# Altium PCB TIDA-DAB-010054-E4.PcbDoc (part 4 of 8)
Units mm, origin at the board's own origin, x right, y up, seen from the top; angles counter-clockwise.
Board outline 300 x 180 mm, 4 copper layers (Top Layer, Inner Layer1, Inner Layer2, Bottom Layer), stack 1.605 mm thick; 873 components, 388 nets, 2405 pads, 1542 vias.
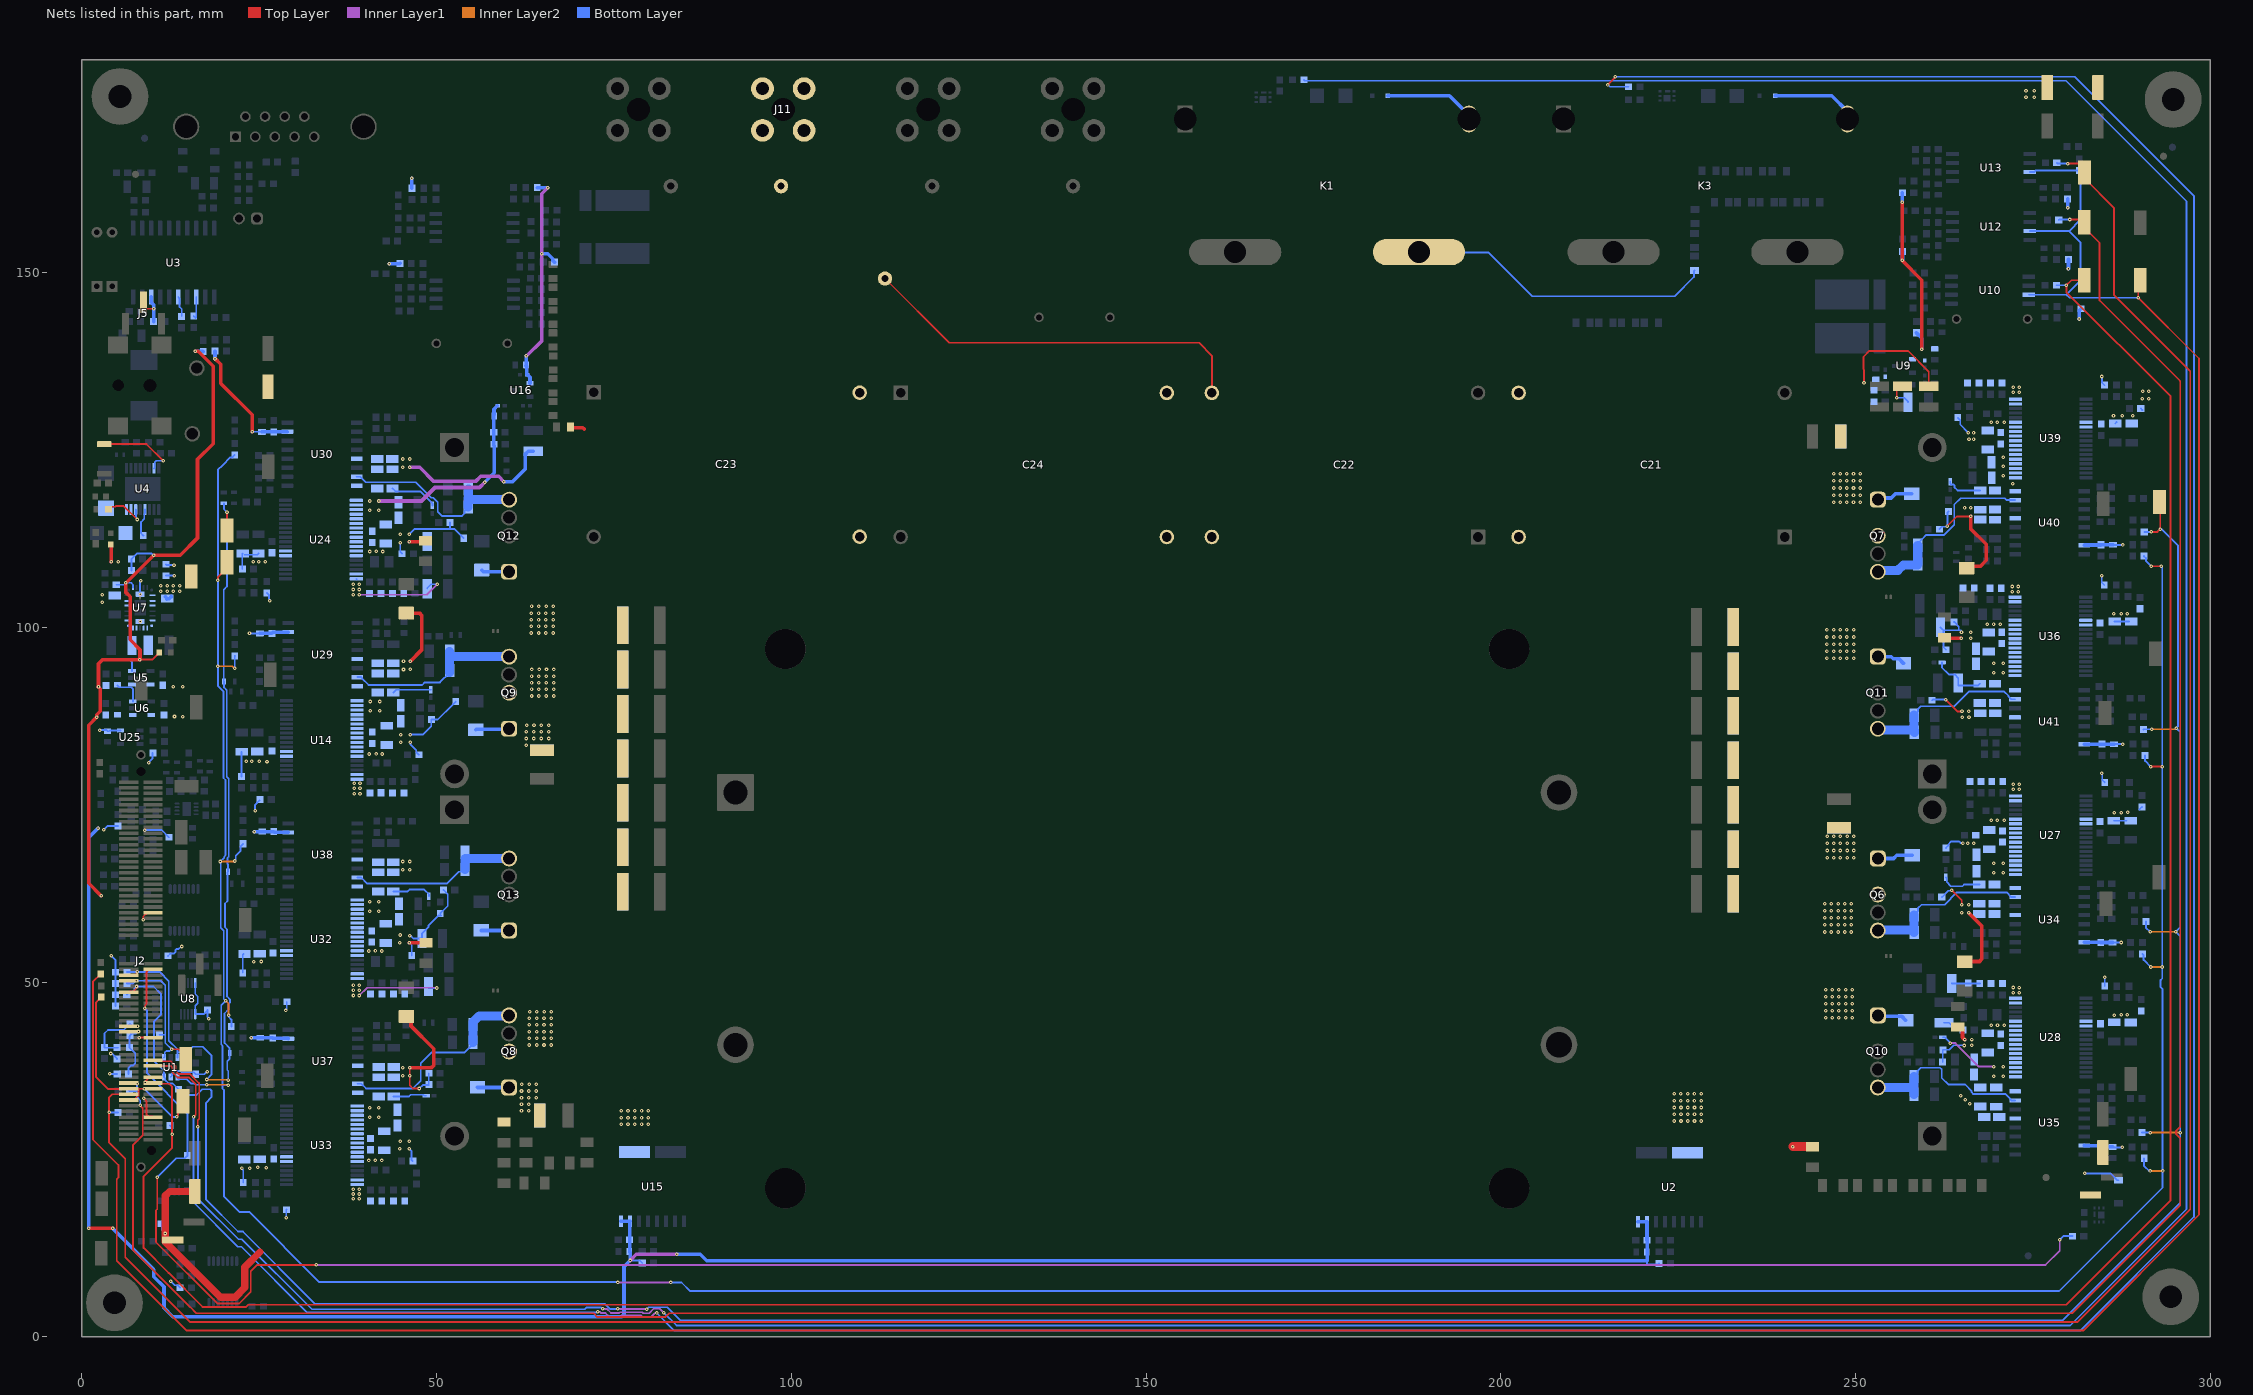
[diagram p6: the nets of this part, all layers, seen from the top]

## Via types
v1: diameter 0.5, hole 0.2, Top Layer to Bottom Layer, tented both sides, 1530 vias
v2: diameter 0.5, hole 0.2, Top Layer to Bottom Layer, 12 vias

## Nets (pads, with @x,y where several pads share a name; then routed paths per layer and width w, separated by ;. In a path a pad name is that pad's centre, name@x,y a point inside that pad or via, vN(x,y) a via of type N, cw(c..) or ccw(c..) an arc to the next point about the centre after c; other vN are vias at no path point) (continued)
3V3_A: C65.1 C110.1 C111.2 C146.1 C147.1 C148.2 L14.2 L15.1 L18.2 R15.2 R37.1 R45.1 R163.1 U2.9 U2.10 U5.5 U15.9 U15.10 U25.5 | length 322.8
  Top Layer w0.508: v1(1.016,15.308) v1(4.372,15.308)
  Inner Layer1 w0.508: v1(77.318,10.77) 78.178,11.63 v1(83.859,11.63)
  Bottom Layer w0.254: v1(2.542,85.502) 3.553,85.502 3.723,85.332 3.875,85.332 4.017,85.474 4.044,85.448 U25.5@5.475,85.448 ; v1(3.139,71.445) 3.701,72.007 R15.2@5.15,72.007 ; v1(8.878,71.409) 8.897,71.428 11.291,71.428 L15.1@12.319,70.4 ; v1(9.448,80.885) 9.448,80.951 9.987,81.49 R163.1@9.987,82.264 ; v1(77.318,10.77) 78.029,10.77 78.036,10.762 78.659,10.762 R45.1@79.007,10.414 ; 220.618,10.744 220.616,10.742 220.616,10.222 222.173,10.222 R37.1@222.288,10.338
  Bottom Layer w0.508: v1(1.016,15.308) 1.016,70.366 v1(2.325,71.675) ; v1(4.372,15.308) 10.196,9.484 10.196,8.478 11.623,7.05 11.623,4.086 12.864,2.845 76.151,2.845 76.449,3.142 76.449,9.901 v1@77.2,10.652 ; v1(43.378,151.23) 43.398,151.25 44.849,151.25 L18.2@44.884,151.285 ; L14.2@46.559,161.867 v1(46.559,163.283) ; U15.10@76.022,16.309 U15.9@77.292,16.309 ; C148.2@77.225,12.024 77.318,11.932 v1(77.318,10.77) ; C148.2@77.225,12.245 C147.1@77.225,13.702 77.275,13.752 U15.9@77.275,16.12 ; v1(83.859,11.63) 87.201,11.63 88.087,10.744 220.618,10.744 220.618,11.938 220.62,11.94 C110.1@220.62,13.62 220.603,13.638 U2.9@220.603,16.205 ; U2.10@219.315,16.205 U2.9@220.585,16.205
  other v1: 12.904,91.603 14.262,91.603
3V3_D: C1.1 C69.1 C186.2 C187.2 C191.2 C192.2 C228.2 C229.2 C233.2 C234.2 C266.2 C268.2 C274.2 C298.2 C306.2 C307.2 C310.2 C311.2 C313.1 L2.2 L8.2 L9.2 L10.2 R79.1 R82.1 R123.2 R164.2 R172.1 R185.1 R187.1 R204.1 R205.1 R230.1 R243.1 R245.1 R286.1 R291.1 R329.1 R344.1 U1.5 U6.5 U8.5 U8.6 U29.15 U30.15 U34.15 U35.15 U37.15 U38.15 U40.15 U41.15 | length 98.7
  Top Layer w0.508: v1(18.808,137.859) 19.625,137.043 19.625,134.361 24.036,129.95 v1(24.036,127.541)
  Bottom Layer w0.254: v1(3.981,37.059) R123.2@5.029,37.059 ; v1@4.136,39.98 v1(4.091,39.935) 4.138,39.888 4.321,39.888 5.004,39.205 R164.2@5.004,39.18 ; v1(4.172,53.688) 4.795,53.065 R205.1@4.795,51.39 4.769,51.364 R82.1@4.769,48.223 R79.1@4.769,46.633 ; R172.1@12.182,53.672 12.552,54.043 13.078,54.043 13.227,54.191 13.227,54.476 13.42,54.669 13.693,54.669 14.04,55.016 v1(14.106,55.016) ; v1(12.578,7.855) 13.146,7.287 13.542,7.287 R230.1@13.89,6.939 ; U1.5@12.578,36.642 12.751,36.815 12.751,37.102 13.121,37.472 13.935,37.472 14.118,37.288 15.815,37.288 C1.1@16.098,37.005 17.271,37.005 17.63,37.364 v1(17.697,37.364) ; U8.5@16.025,49.881 16.025,48.314 16.37,47.97 16.37,47.001 16.025,46.657 U8.6@16.025,45.481 17.202,45.481 C313.1@17.752,46.031 ; C313.1@17.752,46.056 C313.1@17.752,46.031 ; v1(17.929,44.809) 17.929,44.876 17.752,45.053 C313.1@17.752,46.031 ; v1(23.667,99.127) C186.2@25.134,99.127 ; v1(24.036,127.541) 25.391,127.541 C191.2@25.411,127.522 ; v1(24.46,74.143) 24.46,74.968 24.71,75.217 24.71,75.242 25.058,75.59 R185.1@25.083,75.59 ; R187.1@26.086,104.854 26.434,104.506 26.434,103.934 26.544,103.823 v1(26.544,103.757) ; v1(28.753,45.999) 28.753,46.066 28.931,46.244 R286.1@28.931,47.219 ; v1(28.854,16.815) 28.854,17.907 R291.1@28.88,17.932 ; v1(284.688,107.278) 284.688,106.302 R344.1@285.033,105.957 ; v1(284.708,79.402) 284.751,79.359 284.751,78.48 R243.1@285.099,78.132 ; v1(284.708,135.338) 284.722,135.324 284.722,134.457 R329.1@285.07,134.109 ; R245.1@285.105,49.433 v1(285.105,50.688) ; C233.2@286.199,26.783 286.283,26.699 v1(287.596,26.699) v1@287.599,26.696 ; C228.2@286.2,55.574 v1(287.425,55.574) ; C306.2@286.287,111.628 286.319,111.596 v1(287.645,111.596) ; C310.2@286.4,83.535 v1(287.625,83.535)
  Bottom Layer w0.508: v1(18.808,137.859) L2.2@18.808,138.909 ; v1(23.905,42.147) C266.2@25.19,42.147 ; v1(24.332,71.2) 25.453,71.2 C298.2@27.101,71.2 27.168,71.133 29.07,71.133 U38.15@29.116,71.087 ; C186.2@25.134,99.127 25.143,99.136 26.821,99.136 C187.2@26.83,99.145 26.96,99.274 29.07,99.274 U29.15@29.116,99.32 ; C266.2@25.299,42.147 C268.2@26.962,42.147 ; C191.2@25.411,127.522 C192.2@27.079,127.522 27.099,127.541 28.996,127.541 U30.15@29.015,127.561 ; C268.2@26.962,42.061 29.109,42.061 U37.15@29.155,42.015 ; v1(279.871,159.13) L10.2@279.871,160.357 ; v1(279.991,150.54) L9.2@279.991,151.842 ; v1(281.525,143.437) 281.525,144.663 281.746,144.884 L8.2@281.762,144.884 ; U41.15@282.205,83.501 282.222,83.518 284.689,83.518 C311.2@284.706,83.535 C310.2@286.4,83.535 ; U35.15@282.225,26.978 282.271,26.932 284.558,26.932 284.706,26.783 C233.2@286.199,26.783 ; U34.15@282.225,55.625 282.25,55.6 284.5,55.6 C229.2@284.525,55.574 C228.2@286.2,55.574 ; U40.15@282.225,111.561 282.258,111.595 284.546,111.595 C307.2@284.579,111.628 C306.2@286.287,111.628
  other v1: 14.242,87.409 13.097,87.42
5V: C63.1 C64.2 C67.1 C68.2 C71.1 C72.1 C76.1 C77.1 D10.2 J2.48 J2.84 J2.98 J2.112 L1.2 R80.2 U5.1 U5.3 U6.1 U6.3 U7.7 U7.8 U7.9 U7.10 U7.12 U7.13 U7.14 U7.15 U7.22 U7.30 | length 120.3
  Top Layer w0.254: v1(8.15,42.179) J2.84@10.069,42.179 ; v1(8.232,95.447) 9.97,95.447 D10.2@10.958,96.435 ; v1(8.698,58.777) 8.698,59.244 9.233,59.779 J2.48@10.069,59.779 ; v1(8.745,33.65) 9.138,33.257 9.138,31.392 9.429,31.102 9.946,31.102 J2.112@10.069,30.979 ; v1(8.975,35.845) 9.022,35.892 9.022,36.049 9.429,36.456 9.946,36.456 J2.98@10.069,36.579
  Top Layer w0.508: v1@2.387,91.576 2.634,91.329 2.634,88.148 2.158,87.672 v1(2.158,87.343) 1.016,86.201 1.016,63.915 v1(2.752,62.179) ; v1(2.387,91.603) 2.387,94.843 2.992,95.447 v1(8.232,95.447) 8.232,96.846 6.854,98.224 6.854,104.3 6.257,104.898 v1(6.257,106.266) ; v1@6.293,106.266 v1(10.173,110.146) 13.918,110.146 16.339,112.566 16.339,123.654 18.542,125.857 18.542,136.779 16.433,138.888 v1(16.026,138.888)
  Bottom Layer w0.254: C77.1@4.892,106 5.991,106 v1(6.257,106.266) 6.983,106.266 7.249,106 7.249,105.587 U7.22@7.251,105.585 ; C64.2@5.058,91.833 5.334,91.556 7.021,91.556 7.232,91.345 7.232,89.556 U6.3@7.226,89.55 ; 6.854,95.346 7.108,95.092 U5.3@7.108,93.842 ; C76.1@7.015,109.602 C76.1@7.022,109.595 ; R80.2@7.022,107.986 C76.1@7.022,109.595 ; v1(10.173,110.146) 10.077,110.146 9.816,110.407 7.846,110.407 7.034,109.595 C76.1@7.022,109.595
  Bottom Layer w0.508: v1(16.026,138.888) 17.108,138.888 L1.2@17.147,138.849
  other v1: 8.251,100.81
5V_ISO_P: C117.2 C118.1 L13.2 L17.2 U16.1 | length 33
  Inner Layer1 w0.508: v1(62.662,138.243) 62.748,138.243 64.838,140.333 64.838,152.644 v1(64.842,152.649) 64.838,152.653 64.838,161.097 v1(65.681,161.94)
  Bottom Layer w0.508: C118.1@62.632,136.866 62.747,136.751 62.747,135.577 62.751,135.573 C117.2@62.835,135.573 ; v1(62.662,138.243) 62.668,138.237 C118.1@62.668,136.988 ; C117.2@62.793,135.573 C117.2@62.835,135.573 ; U16.1@63.197,134.376 63.197,135.212 C117.2@62.835,135.573 ; L13.2@64.231,161.94 v1(65.681,161.94) ; v1(64.842,152.649) 65.695,152.649 66.412,151.931 66.412,151.681 66.633,151.46 L17.2@66.658,151.46
5V_ISO_S: C86.2 C87.1 L7.2 L11.2 L12.2 U9.1 | length 27.2
  Top Layer w0.508: v1(256.553,159.875) 256.553,159.286 256.55,159.283 256.55,151.683 259.33,148.903 v1(259.33,139.173)
  Bottom Layer w0.508: v1(256.553,159.875) 256.582,159.905 L12.2@256.582,161.232 ; v1(256.56,151.7) 256.598,151.738 L11.2@256.598,152.96 ; L7.2@258.565,141.498 258.565,141.473 258.786,141.252 258.811,141.252 259.33,140.732 v1(259.33,139.173)
12V: C73.1 C74.1 C75.1 C96.1 C112.1 C113.1 C138.1 C145.1 C149.1 C150.1 C155.1 C156.1 C157.1 C158.1 C198.1 C199.1 C200.1 C201.1 C237.1 C238.1 C275.1 C276.1 C314.1 C325.1 C326.1 C327.1 C328.1 C329.1 C330.1 C331.1 C332.1 D1.1 D3.1 D5.2 D8.2 D9.1 D13.1 D16.1 J1.1 J3.1 K1.2 K3.2 R186.2 R190.2 R244.2 R248.2 R287.2 R292.2 R330.2 R345.2 TP6.1 U4.15 U4.16 U7.2 U7.3 U7.4 U7.18 U7.19 U14.6 U14.7 U24.6 U24.7 U27.6 U27.7 U28.6 U28.7 U32.6 U32.7 U33.6 U33.7 U36.6 U36.7 U39.6 U39.7 | length 84.9
  Top Layer w0.508: D8.2@4.134,111.656 4.16,111.63 4.16,109.26 v1(4.18,109.24)
  Top Layer w1.016: C73.1@15.977,20.483 15.958,20.502 12.382,20.502 11.787,19.906 v1(11.787,14.567) 11.787,13.388 19.588,5.587 21.649,5.587 23.013,6.951 23.013,9.83 25.146,11.963
  Bottom Layer w0.254: D13.1@11.333,15.921 11.333,15.02 v1(11.787,14.567) ; R186.2@22.53,78.981 22.53,82.398 C325.1@22.581,82.448 ; v1(22.606,23.749) 22.606,23.682 22.784,23.505 R292.2@22.784,21.755 ; R190.2@22.657,108.204 22.657,110.338 C326.1@22.708,110.388 ; R287.2@22.712,51.3 22.712,53.824 C329.1@22.86,53.971 ; C326.1@22.962,110.213 24.753,110.213 C157.1@24.936,110.397 ; v1(282.261,23.044) 285.918,23.044 286.88,22.083 D16.1@287.032,22.083 ; C198.1@286.4,72.737 C327.1@288.165,72.737 ; C237.1@286.488,100.812 288.493,100.812 C331.1@288.513,100.792 ; C275.1@286.588,128.713 C275.1@286.78,128.905 ; R244.2@289.999,74.337 290.347,74.685 R244.2@290.347,74.689 ; R330.2@290.18,130.835 R330.2@290.414,130.601
  Bottom Layer w0.508: C74.1@11.781,104.322 C74.1@12.067,104.035 ; C74.1@12.01,103.978 C74.1@12.067,104.035 ; C74.1@12.67,104.331 12.374,104.035 C74.1@12.067,104.035 ; D1.1@184.084,174.904 192.756,174.904 195.52,172.14 K1.2@195.52,171.62 ; D3.1@238.66,174.88 246.651,174.88 248.84,172.691 K3.2@248.84,171.62
  other v1: 23.698,23.774 26.01,23.825 24.838,23.894 286.45,45.342 287.401,45.39 288.265,45.39 24.282,52.883 25.321,52.9 286.45,73.888 287.401,73.889 288.315,73.914 26.137,81.077 23.19,81.102 24.003,81.102 25.07,81.102 286.36,101.93 287.401,101.93 288.29,101.93 2.901,103.534 2.935,104.585 11.186,105.075 12.085,105.075 12.935,105.075 13.835,105.075 11.186,105.865 12.074,105.865 12.935,105.865 13.824,105.865 5.155,109.24 24.181,109.245 24.944,109.24 25.883,109.245 286.334,129.794 287.553,129.794 289.052,129.794 291.313,132.2 290.4,132.224 290.438,133.248 291.313,133.248 274.006,174.7 275.18,174.7 274.006,175.6 275.18,175.6
+15V_BOT1: C167.1 C168.1 C176.2 C177.2 C181.2 C182.2 R6.1 R24.2 R129.1 R154.2 R191.2 R227.1 U24.28 U24.29 U30.5 | length 37.8
  Top Layer w0.508: v1(46.199,112.035) 48.305,112.035 R6.1@48.467,112.197
  Inner Layer1 w0.508: v1(46.255,122.548) 47.64,122.548 49.639,120.55 55.529,120.55 56.239,121.26 58.776,121.26 v1(59.512,120.523)
  Bottom Layer w0.254: v1(44.898,111.931) 44.898,110.641 R191.2@45.182,110.357 ; v1(46.199,112.035) 48.655,112.035 R227.1@48.717,112.097 ; v1(46.199,113.12) 46.907,113.828 51.919,113.828 ; R24.2@51.936,114.747 51.919,114.729 51.919,113.828 ; R154.2@53.858,112.535 53.858,112.56 52.589,113.828 51.919,113.828
  Bottom Layer w0.508: v1(59.512,120.523) 60.731,120.523 62.551,122.343 62.551,124.421 62.947,124.817 R129.1@63.647,124.817
  other v1: 44.898,113.12 45.276,122.529 45.276,123.706 46.255,123.706
+15V_BOT2: C244.1 C245.1 C255.2 C256.2 C260.2 C261.2 R20.1 R31.2 R229.2 R289.2 R317.2 U32.28 U32.29 U38.5 | length 14.7
  Top Layer w0.508: v1(46.2,55.547) R20.1@48.534,55.546
  Bottom Layer w0.254: v1(46.2,55.547) 46.525,55.221 R289.2@46.525,53.726 ; v1(46.279,56.503) 46.375,56.503 46.741,56.137 R229.2@47.968,56.137 47.968,56.837 48.873,57.742 48.873,57.95 49.349,58.426 50.322,59.399 R31.2@50.654,59.399 ; R31.2@50.564,59.673 50.564,59.698 50.912,60.046 50.937,60.046 51.613,60.722 51.613,62.375 51.016,62.972 R317.2@50.991,62.972
  other v1: 44.864,55.544 44.898,56.632 45.272,65.811 46.25,65.83 45.272,66.988 46.25,66.988
+15V_BOT3: C210.1 C211.1 C218.2 C219.2 C223.2 C224.2 R7.1 R27.2 R249.2 R273.2 R340.2 U28.28 U28.29 U35.5 | length 11.9
  Top Layer w0.508: R7.1@264.386,43.67 264.661,43.67 265.057,43.274 265.057,42.197 v1(265.351,41.903)
  Bottom Layer w0.254: R273.2@262.268,38.748 262.268,40.458 263.203,40.458 263.836,41.091 264.473,41.091 265.293,41.091 v1(265.32,41.064) ; R340.2@262.46,44.266 263.16,44.266 264.165,43.261 R249.2@265.111,43.261 ; R249.2@265.104,43.254 265.104,42.217 265.351,41.97 v1(265.351,41.903)
  other v1: 266.081,32.853 265.471,33.446 264.786,33.954 266.348,41.077 266.348,41.903
+15V_BOT4: C285.1 C286.1 C294.2 C295.2 C300.2 C301.2 R21.1 R34.2 R338.1 R346.2 R369.2 U36.28 U36.29 U41.5 | length 15.1
  Top Layer w0.254: v1(262.674,89.801) 264.328,88.147 v1(264.989,88.147)
  Top Layer w0.508: R21.1@262.512,98.532 262.62,98.425 v1(264.893,98.425)
  Bottom Layer w0.254: R369.2@260.781,89.708 260.873,89.801 v1(262.674,89.801) ; R338.1@261.95,100.004 262.227,99.727 262.382,99.572 262.382,97.19 262.73,96.842 R34.2@262.745,96.842 ; R338.1@262.386,99.568 264.541,99.568 ; R346.2@263.867,100.755 263.892,100.755 264.24,100.407 264.24,100.382 264.541,100.081 264.541,99.568 ; v1(264.919,99.267) 264.872,99.314 264.872,99.568 264.541,99.568
  other v1: 264.995,87.311 265.974,87.311 265.968,88.147 266.194,98.425 266.194,99.292
+15V_SEN_SEC: R88.1 R339.2 | length 4
  Top Layer w0.254: v1(255.797,132.342) 255.797,133.422 256.32,133.945 R339.2@256.592,133.945
  Bottom Layer w0.254: v1(255.797,132.342) 256.838,132.342 257.361,131.819 R88.1@257.361,131.7
+15V_TOP1: C165.1 C166.1 C173.2 C174.2 C178.2 C179.2 D24.1 R25.2 R188.2 R208.2 U14.28 U14.29 U29.5 | length 20.6
  Top Layer w0.508: D24.1@45.778,101.999 47.62,101.999 47.917,101.701 47.917,96.789 v1(46.35,95.222)
  Bottom Layer w0.254: v1(46.3,83.781) 46.347,83.734 46.347,83.56 46.368,83.539 46.368,83.452 47.172,82.648 47.172,82.377 47.52,82.029 R188.2@47.545,82.029 ; v1(46.312,84.875) 46.33,84.893 48.139,84.893 49.281,86.035 49.281,86.965 R25.2@49.301,86.986 50.165,86.986 52.356,89.177 52.381,89.177 52.729,89.525 R208.2@52.729,89.55
  other v1: 44.964,83.778 44.998,84.866 45.372,94.045 46.35,94.064 45.372,95.222
+15V_TOP2: C246.1 C247.1 C252.2 C253.2 C257.2 C258.2 D29.1 R32.2 R293.2 R311.2 U33.28 U33.29 U37.5 | length 21.2
  Top Layer w0.254: v1(46.25,37.948) v1(46.25,36.79) 46.25,35.446 46.695,35.002 v1(47.595,35.002)
  Top Layer w0.508: D29.1@45.773,45.147 45.794,45.147 46.43,44.511 46.43,43.803 49.618,40.615 49.618,38.246 49.32,37.948 v1(46.25,37.948)
  Bottom Layer w0.254: v1(46.2,26.507) 46.482,26.225 46.482,24.98 R293.2@46.682,24.78 ; v1(47.595,35.002) 48.07,35.477 48.934,35.477 48.939,35.482 R311.2@48.939,37.155
  other v1: 44.864,26.504 44.898,27.592 46.2,27.592 45.272,36.771 45.272,37.948
+15V_TOP3: C208.1 C209.1 C215.2 C216.2 C220.2 C221.2 D28.1 R26.2 R246.2 R267.2 U27.28 U27.29 U34.5 | length 17.2
  Top Layer w0.254: v1(263.558,62.929) 264.957,61.53 264.957,60.911 v1(264.97,60.899)
  Top Layer w0.508: D28.1@265.367,52.885 265.387,52.905 267.449,52.905 267.747,53.203 267.747,57.943 v1(265.949,59.741)
  Bottom Layer w0.254: R267.2@262.14,61.975 262.165,61.975 263.072,62.882 263.511,62.882 v1(263.558,62.929) ; R26.2@262.716,68.897 263.064,69.245 263.064,69.391 263.499,69.826 264.565,69.826 264.785,69.606 265.077,69.606 v1(265.124,69.559)
  other v1: 264.97,59.741 265.949,60.918 266.619,69.536 265.815,69.559
+15V_TOP4: C280.1 C281.1 C291.2 C292.2 C296.2 C297.2 D30.1 R35.2 R331.2 R362.2 U39.28 U39.29 U40.5 | length 20.2
  Top Layer w0.254: v1(262.931,114.264) 264.287,115.62 v1(266.194,115.62)
  Top Layer w0.508: D30.1@265.637,108.325 265.886,108.574 267.548,108.574 268.395,109.421 268.395,111.697 266.194,113.899 v1(266.194,115.62)
  Bottom Layer w0.254: R362.2@261.8,113.811 262.148,114.159 262.759,114.159 262.864,114.264 v1(262.931,114.264) 262.931,116.15 R35.2@263.078,116.297 ; R331.2@264.405,129.508 264.753,129.16 264.753,128.576 v1(265.892,127.436)
  other v1: 265.346,116.83 266.194,116.83 265.974,126.521 266.613,126.521 266.613,127.436
-4V_BOT1: C119.2 C120.1 C163.2 C164.2 C167.2 C168.2 C171.1 C172.1 C176.1 C177.1 D17.1 R14.2 R131.1 R198.1 R199.1 R219.1 U24.19 U24.20 U24.21 U24.22 U24.23 U24.24 U24.25 U24.26 U24.27 U24.30 U24.31 U24.35 U24.36 U30.8 | length 47.7
  Inner Layer1 w0.254: v1(39.155,104.593) 48.656,104.593 v1(50.113,106.049)
  Inner Layer1 w0.508: v1(41.898,117.794) 47.908,117.794 49.81,119.697 56.07,119.697 v1(56.82,120.447)
  Bottom Layer w0.254: U24.36@38.715,106.835 38.715,106.797 U24.36@38.775,106.737 ; C177.1@43.817,119.565 44.24,119.142 47.736,119.142 49.082,117.797 49.097,117.797 49.443,117.452 D17.1@49.443,117.177 ; R219.1@48.717,105.422 48.717,105.526 49.24,106.049 v1(50.113,106.049)
  Bottom Layer w0.508: v1(56.82,120.447) 58.156,121.783 58.156,125.582 58.091,125.646 R131.1@58.091,127.467 C119.2@58.091,129.95 ; C119.2@58.116,129.95 58.116,130.735 C120.1@58.595,131.214
  other v1: 38.318,104.593 38.318,105.318 39.155,105.317 38.318,106.042 39.155,106.042 40.601,110.678 42.431,110.678 41.556,110.685 40.603,116.461 41.894,116.461 40.593,117.794
-4V_BOT2: C240.2 C241.2 C244.2 C245.2 C250.1 C251.1 C255.1 C256.1 D31.1 R221.2 R298.1 R299.1 U32.19 U32.20 U32.21 U32.22 U32.23 U32.24 U32.25 U32.26 U32.27 U32.30 U32.31 U32.35 U32.36 U38.8 | length 18.3
  Inner Layer1 w0.254: v1(39.155,48.105) 40.259,49.209 50.035,49.209 v1(50.082,49.162)
  Bottom Layer w0.254: C256.1@43.946,62.771 45.961,62.771 46.219,63.029 48.306,63.029 48.957,62.378 D31.1@48.957,62.103 ; R221.2@48.885,49.162 v1(50.082,49.162)
  other v1: 38.318,48.105 38.318,48.83 39.155,48.829 38.318,49.554 39.155,49.554 40.465,54.379 41.42,54.386 42.295,54.379 40.603,59.973 41.894,59.973 40.594,61.306 41.898,61.306
-4V_BOT3: C206.2 C207.2 C210.2 C211.2 C213.1 C214.1 C218.1 C219.1 D23.1 R257.1 R258.1 R381.2 U28.19 U28.20 U28.21 U28.22 U28.23 U28.24 U28.25 U28.26 U28.27 U28.30 U28.31 U28.35 U28.36 U35.8 | length 12.9
  Inner Layer1 w0.254: v1(263.331,41.407) 263.335,41.403 264.056,41.403 267.371,38.088 v1(269.486,38.088)
  Bottom Layer w0.254: D23.1@262.268,42.217 262.543,42.217 263.331,41.428 v1(263.331,41.407) ; R381.2@263.53,49.8 263.54,49.81 267.502,49.81 C207.2@267.505,49.807
  other v1: 269.482,36.755 270.786,36.755 270.777,38.088 269.99,43.926 269.115,43.933 270.945,43.933 272.225,48.507 273.062,48.507 272.225,49.232 273.062,49.231
-4V_BOT4: C283.2 C284.2 C285.2 C286.2 C289.1 C290.1 C294.1 C295.1 D33.1 R350.1 R351.1 R379.1 U36.19 U36.20 U36.21 U36.22 U36.23 U36.24 U36.25 U36.26 U36.27 U36.30 U36.31 U36.35 U36.36 U41.8 | length 8.4
  Bottom Layer w0.254: D33.1@262.173,95.031 262.173,94.316 263.141,93.348 263.936,93.348 264.459,92.825 264.459,91.81 C295.1@267.287,91.81 ; C295.1@267.287,91.81 C295.1@267.518,92.041 ; C295.1@267.287,91.81 C295.1@267.518,92.041 ; C295.1@267.287,91.81 C295.1@267.518,92.041
  other v1: 269.482,93.608 270.786,93.608 269.486,94.941 270.777,94.941 268.556,100.407 269.43,100.399 270.385,100.407 272.059,105.021 272.896,105.021 272.059,105.745 272.896,105.745
-4V_SEN_SEC: C90.2 C91.1 R13.2 R87.1 R380.2 | length 16.5
  Top Layer w0.254: v1(251.181,134.442) 251.181,136.266 251.102,136.344 251.102,138.101 251.939,138.938 257.374,138.938 260.298,136.014 R380.2@260.298,133.945
-4V_TOP1: C161.2 C162.2 C165.2 C166.2 C169.1 C170.1 C173.1 C174.1 D20.1 R196.1 R197.1 U14.19 U14.20 U14.21 U14.22 U14.23 U14.24 U14.25 U14.26 U14.27 U14.30 U14.31 U14.35 U14.36 U29.8 | length 5.5
  Bottom Layer w0.254: C174.1@43.936,90.785 44.348,91.197 D20.1@49.24,91.197
  other v1: 38.404,76.566 39.241,76.566 38.404,77.291 39.241,77.291 38.404,78.015 39.241,78.015 40.546,82.136 41.501,82.144 42.375,82.136 40.704,88.207 41.994,88.207 40.694,89.54 41.998,89.54
-4V_TOP2: C242.2 C243.2 C246.2 C247.2 C248.1 C249.1 C252.1 C253.1 D32.1 R301.1 R302.1 U33.19 U33.20 U33.21 U33.22 U33.23 U33.24 U33.25 U33.26 U33.27 U33.30 U33.31 U33.35 U33.36 U37.8 | length 4.8
  Bottom Layer w0.254: C253.1@43.966,33.89 46.144,33.89 46.377,34.123 48.164,34.123 48.294,33.993 D32.1@48.569,33.993
  other v1: 38.318,19.45 39.154,19.45 38.318,20.135 39.154,20.135 38.318,20.819 39.154,20.819 40.446,24.862 41.401,24.87 42.275,24.862 40.603,30.933 41.894,30.933 40.594,32.266 41.898,32.266
-4V_TOP3: C196.1 C204.2 C205.2 C208.2 C209.2 C212.1 C215.1 C216.1 D21.1 R255.1 R256.1 U27.19 U27.20 U27.21 U27.22 U27.23 U27.24 U27.25 U27.26 U27.27 U27.30 U27.31 U27.35 U27.36 U34.8 | length 5.6
  Bottom Layer w0.254: D21.1@262.716,64.759 262.839,64.636 262.839,64.107 263.43,63.516 265.059,63.516 265.289,63.746 C216.1@267.446,63.746
  other v1: 269.482,65.403 270.786,65.403 269.486,66.736 270.777,66.736 269.105,72.807 269.979,72.799 270.934,72.807 272.225,77.155 273.062,77.155 272.225,77.879 273.062,77.879
-4V_TOP4: C278.2 C279.2 C280.2 C281.2 C287.1 C288.1 C291.1 C292.1 D34.1 R335.1 R336.1 U39.19 U39.20 U39.21 U39.22 U39.23 U39.24 U39.25 U39.26 U39.27 U39.30 U39.31 U39.35 U39.36 U40.8 | length 5
  Bottom Layer w0.254: D34.1@263.332,120.533 263.332,120.258 263.455,120.135 263.763,120.135 263.912,119.986 263.912,119.717 264.353,119.276 267.52,119.276 C292.1@267.534,119.261
  other v1: 272.149,120.198 270.786,121.339 270.777,122.672 270.787,123.967 269.084,128.88 269.958,128.872 270.914,128.88 272.225,133.091 273.062,133.091 272.225,133.816 273.062,133.815
\DESAT_PRI: C319.2 J2.61 R147.1 R150.1 R205.2 R212.1 R213.1 TP21.1 U1.3 | length 117.1
  Top Layer w0.254: J2.61@6.669,50.979 7.635,50.979 J2.61@7.809,51.153 ; TP21.1@20.495,113.643 v1(20.495,116.228)
  Inner Layer2 w0.254: v1(17.649,36.272) 17.688,36.233 20.647,36.233 v1(20.686,36.195)
  Bottom Layer w0.254: R205.2@6.395,51.39 6.431,51.427 v1(7.856,51.427) 11,51.427 12.289,50.137 12.289,41.754 13.528,40.516 13.528,40.117 ; U1.3@13.528,39.392 13.528,40.117 ; v1(17.649,36.272) 18.304,36.927 18.304,39.665 17.094,40.875 15.687,40.875 14.882,40.07 C319.2@14.857,40.07 14.81,40.117 13.528,40.117 ; R150.1@20.072,117.458 20.072,116.651 v1(20.495,116.228) 20.495,105.754 20.038,105.297 20.038,92.391 20.058,92.37 R147.1@20.077,92.351 20.077,91.526 20.454,91.149 20.454,78.946 20.74,78.66 20.74,67.668 20.564,67.492 20.564,66.633 20.633,66.565 R213.1@20.633,65.532 20.585,65.484 20.585,61.438 20.218,61.072 20.218,57.714 20.498,57.435 20.498,47.983 20.901,47.579 20.901,47.099 20.726,46.924 20.726,46.152 20.146,45.572 20.146,41.423 20.837,40.732 20.837,39.119 20.538,38.82 20.538,37.615 20.686,37.467 v1(20.686,36.195)
\DESAT_SEC: C321.1 J2.67 R82.2 R206.1 R207.1 R263.1 R264.1 TP23.1 U1.6 | length 454.7
  Top Layer w0.254: J2.67@6.669,48.579 6.792,48.702 7.308,48.702 7.703,49.096 ; v1(291.647,113.432) 292.529,113.432 v1(292.913,113.816) 292.913,117.564 TP23.1@292.823,117.654
  Inner Layer1 w0.254: v1(75.539,3.943) 79.623,3.943 v1(79.642,3.924)
  Inner Layer2 w0.254: v1(291.487,57.083) v1(295.117,57.083) ; v1(291.523,28.793) v1(295.745,28.793) ; v1(291.756,85.64) v1@294.981,85.64
  Bottom Layer w0.254: R82.2@6.369,48.223 6.671,48.525 7.072,48.525 7.417,48.87 7.417,49.046 v1(7.75,49.379) 10.142,49.379 11.188,48.333 11.188,45.419 10.195,44.426 10.195,38.941 11.032,38.104 11.046,38.104 11.628,37.523 U1.6@11.628,36.642 11.61,36.624 11.801,36.433 11.801,36.182 12.273,35.709 12.843,35.709 13.663,34.889 13.689,34.889 14.037,34.541 14.037,34.232 14.186,34.084 16.202,34.084 17.015,34.896 18.122,34.896 18.304,34.714 18.304,33.764 17.547,33.007 17.547,19.349 22.05,14.846 22.732,14.846 32.959,4.62 73.773,4.62 74.45,3.943 v1(75.539,3.943) ; v1(79.642,3.924) 79.647,3.924 79.914,4.19 82.54,4.19 84.39,2.34 279.158,2.34 295.74,18.922 v1@295.74,28.788 ; R207.1@290.36,28.788 291.518,28.788 v1(291.523,28.793) ; R264.1@290.561,85.576 290.625,85.64 v1(291.756,85.64) ; R263.1@290.671,113.432 v1(291.647,113.432) ; R206.1@290.9,58.533 290.9,57.67 v1(291.487,57.083) ; v1(292.913,113.816) 293.144,113.816 295.405,111.555 295.405,86.025 295.16,85.78 v1(295.16,85.753) 295.226,85.753 295.539,85.441 295.56,85.441 295.74,85.261 295.74,57.706 v1(295.117,57.083) 295.745,56.455 v1@295.745,28.798
\FLT_EFUSE: R70.1 U4.14 | length 6.5
  Top Layer w0.254: R70.1@3.816,116.631 4.164,116.979 4.726,116.979 4.824,117.077 5.959,117.077 v1(7.851,115.185)
  Bottom Layer w0.254: U4.14@7.632,116.587 7.676,116.543 7.676,115.456 7.851,115.282 v1(7.851,115.185)
\FLT_PRI: C324.2 J2.79 R164.1 R167.2 | length 10.5
  Top Layer w0.254: J2.79@6.669,43.779 6.694,43.753 v1(7.891,43.753)
  Bottom Layer w0.254: R164.1@5.182,40.742 3.289,40.742 R167.2@3.226,40.805 3.226,42.748 3.725,43.247 5.948,43.247 6.795,44.094 C324.2@6.82,44.094 7.161,43.753 v1(7.891,43.753)
\FLT_SEC: C323.2 J2.81 R123.1 R125.2 | length 9.1
  Top Layer w0.254: J2.81@6.669,42.979 6.696,43.006 7.999,43.006 v1(8.026,43.033)
  Bottom Layer w0.254: R123.1@6.629,37.059 6.629,37.915 6.943,38.229 7.247,38.229 7.562,38.543 7.562,39.949 6.756,40.755 R125.2@6.756,40.78 6.756,42.355 C323.2@6.82,42.418 7.168,42.766 7.692,42.766 7.959,43.033 v1(8.026,43.033)
\RST: R214.1 R220.1 R279.1 R280.1 R323.1 R324.1 R375.1 R376.1 TP22.1 U1.4 | length 518.8
  Top Layer w0.254: v1(19.221,106.622) 19.221,107.05 20.495,108.325 TP22.1@20.495,109.15 ; v1(291.579,80.368) v1(293.213,80.368) ; v1@291.669,108.584 v1@293.078,108.584
  Inner Layer1 w0.254: v1(75.539,7.669) v1(83.015,7.669)
  Inner Layer2 w0.254: v1(17.644,35.541) 20.529,35.541 20.62,35.451 v1(20.686,35.451) ; v1(19.221,94.495) 21.264,94.495 21.533,94.225 v1(21.6,94.225) ; v1(19.553,66.988) 21.431,66.988 21.506,67.063 v1(21.602,67.063) ; v1(20.321,47.339) 20.727,46.934 v1(20.727,45.332) ; v1(291.523,23.38) v1(293.248,23.38) ; v1(291.577,52.122) v1(293.213,52.122)
  Bottom Layer w0.254: U1.4@13.528,36.642 13.528,36.493 13.701,36.32 14.83,36.32 15.456,35.694 15.925,35.694 16.078,35.541 v1(17.644,35.541) ; v1@19.506,66.947 20.107,67.548 20.107,67.682 20.283,67.858 20.283,78.471 19.997,78.757 19.997,90.956 19.209,91.744 19.209,94.484 v1(19.221,94.495) v1(19.221,106.622) 19.221,122.19 19.888,122.857 20.962,123.931 21.252,123.931 21.6,124.279 R214.1@21.6,124.299 ; v1(19.553,66.988) 19.601,66.941 19.601,66.767 19.609,66.759 19.609,57.678 20.041,57.246 20.041,47.62 v1(20.321,47.339) 19.689,46.707 19.689,41.219 19.868,41.04 19.868,35.541 ; v1(20.686,35.451) 19.958,35.451 19.868,35.541 ; v1@20.712,45.107 21.114,44.706 R323.1@21.114,43.747 ; v1(21.6,94.225) 21.6,95.962 R220.1@21.605,95.967 ; v1@21.726,67.254 21.726,67.821 22.411,68.506 22.411,69.146 R324.1@22.759,69.494 ; v1(75.539,7.669) 75.49,7.719 33.515,7.719 23.626,17.607 22.247,17.607 20.085,19.77 20.085,34.747 19.868,34.964 19.868,35.541 ; v1(83.015,7.669) 84.548,7.669 85.757,6.46 278.657,6.46 293.248,21.052 v1(293.248,23.38) 293.248,49 292.98,49.268 292.98,50.275 293.213,50.508 v1(293.213,52.122) v1(293.213,80.368) 293.213,108.382 293.09,108.505 v1(293.09,108.571) ; R279.1@290.41,53.974 290.576,53.808 290.576,53.123 v1(291.577,52.122) ; R375.1@290.625,110.028 290.928,109.725 290.928,109.325 v1(291.657,108.596) ; R280.1@290.652,25.171 290.652,24.074 291.346,23.38 v1(291.523,23.38) ; R376.1@290.786,81.935 290.786,81.161 v1(291.579,80.368)
\RST_MCU: C320.2 J2.63 R204.2 TP20.1 U1.1 | length 21.5
  Top Layer w0.254: J2.63@6.669,50.179 7.708,50.179 v1(7.71,50.177) ; v1(12.69,40.534) 13.66,40.534 14.422,39.772 TP20.1@14.422,39.194
  Bottom Layer w0.254: R204.2@6.393,49.799 7.274,49.799 7.653,50.177 11.166,50.177 11.805,49.539 11.805,41.418 v1(12.69,40.534) 12.661,40.534 12.418,40.291 11.927,40.291 11.728,40.092 11.728,39.492 U1.1@11.628,39.392 ; C320.2@11,42.569 11.777,42.569
\SHDN_EFUSE: S1.1 U4.7 | length 11.4
  Top Layer w0.254: S1.1@3.199,125.815 9.154,125.815 v1(11.502,123.467)
  Bottom Layer w0.254: U4.7@10.232,122.387 10.327,122.482 10.327,123.245 10.549,123.467 v1(11.502,123.467)
AGND: NT1.2 R83.2 R84.1 U7.24 U7.27 | length 4.3
  Bottom Layer w0.254: v1(8.251,104.66) U7.24@8.251,105.585 8.251,106.497 v1(8.323,106.57) ; R83.2@11.874,108.877 11.989,108.762 v1(13.029,108.762) ; v1(13.042,107.276) R84.1@11.876,107.275 ; R84.1@11.876,107.275 R84.1@11.876,107.275
CAN_EN: J5.2 R52.2 U3.8 | length 5.7
  Top Layer w0.254: J5.2@8.725,145.783 8.725,145.254 9.098,144.881 v1(10.152,144.881)
  Bottom Layer w0.508: U3.8@9.815,146.54 9.815,145.79 10.152,145.453 v1(10.152,144.881) 10.152,144.309 R52.2@10.152,143.086
CAN_RX: R38.2 U3.5 | length 2.9
  Bottom Layer w0.254: U3.5@13.625,146.54 13.798,146.367 13.798,145.173 14.129,144.842 R38.2@14.129,143.839
CAN_TX: R41.2 U3.3 | length 3.3
  Bottom Layer w0.254: R41.2@15.826,143.84 16.07,143.595 16.173,143.698 16.173,143.84 16.173,146.532 U3.3@16.165,146.54
CLK_MOD: R10.1 R118.2 TP24.1 U10.7 U12.7 U13.7 | length 529.9
  Top Layer w0.254: R10.1@2.718,51.159 2.718,51.134 1.6,50.017 1.6,27.813 5.203,24.21 5.203,22.475 4.96,22.232 4.96,10.749 14.82,0.889 282.064,0.889 298.38,17.205 298.38,137.874 v1(289.834,146.42) 289.834,148.813 TP24.1@289.744,148.903
  Bottom Layer w0.254: U10.7@274.39,146.865 279.707,146.865 ; U12.7@274.543,155.827 280.107,155.827 ; U13.7@274.55,164.145 275.15,164.145 275.355,164.35 R118.2@281.525,164.35 281.68,164.195 281.68,157.4 280.107,155.827 ; v1(289.834,146.42) 280.152,146.42 279.707,146.865 ; 279.707,146.865 281.68,148.838 281.68,154.254 280.107,155.827
CLK_MOD_DELAYED: J2.101 J2.102 J2.105 R19.1 TP12.1 | length 31.4
  Top Layer w0.254: R19.1@2.766,47.869 2.766,47.844 2.418,47.496 2.393,47.496 2.057,47.161 2.057,36.576 3.683,34.95 6.64,34.95 J2.101@6.669,34.979 J2.101@8.026,34.979 ; J2.105@6.669,33.379 6.792,33.502 7.492,33.502 8.026,34.036 J2.101@8.026,34.979 ; J2.102@10.069,34.979 v1(8.811,34.979) J2.101@8.026,34.979 ; 13.612,31.252 13.612,32.535 TP12.1@14.3,33.223
  Bottom Layer w0.254: v1(8.811,34.979) 12.785,31.005 v1(13.431,31.005)
D1H_P: C16.1 C20.1 C23.2 C24.2 C26.1 C30.1 D14.1 D26.1 J11.1 Q8.1 Q9.1 R66.2 R112.1 TP3.1 | length 11.6
  Top Layer w0.508: R112.1@68.915,128.237 69.046,128.106 70.649,128.106 70.82,127.935
  Bottom Layer w0.508: D14.1@55.569,85.543 55.675,85.649 60.199,85.649 Q9.1@60.249,85.699 ; D26.1@55.798,35.163 55.821,35.14 Q8.1@60.355,35.14
  Bottom Layer w1.27: Q8.1@60.152,34.937 Q8.1@60.355,35.14
  other v1: 61.995,31.842 63.041,31.842 61.995,32.778 63.041,32.778 61.995,33.713 63.041,33.713 64.086,33.713 61.995,34.649 63.041,34.649 64.086,34.649 62.054,35.585 63.08,35.585 64.105,35.585 62.677,83.386 62.677,84.322 63.722,84.322 64.767,84.322 65.813,84.322 62.677,85.257 63.722,85.257 64.767,85.257 65.813,85.257 62.736,86.193 63.762,86.193 64.787,86.193 65.813,86.193
D1H_S: C15.1 C19.1 C21.2 C22.2 C25.1 C28.1 D18.1 D25.1 K1.4 Q6.1 Q7.1 R96.2 R127.2 TP1.1 | length 112.2
  Top Layer w0.254: TP1.1@113.22,149.14 122.282,140.078 157.476,140.078 159.289,138.265 C22.2@159.289,133.02
  Top Layer w1.27: v1(241.142,26.796) R127.2@243.9,26.796
  Bottom Layer w0.254: K1.4@188.47,152.87 188.54,152.8 198.274,152.8 204.434,146.64 224.49,146.64 227.225,149.375 227.225,150.223 R96.2@227.3,150.298
  Bottom Layer w0.508: Q6.1@253.126,67.42 255.329,67.42 255.784,67.875 D18.1@257.991,67.875 ; Q7.1@253.126,117.979 253.365,118.218 255.008,118.218 255.614,118.823 D25.1@257.917,118.823
  other v1: 245.988,67.546 246.923,67.546 247.859,67.546 248.794,67.546 249.734,67.546 245.988,68.541 246.923,68.541 247.859,68.541 248.794,68.541 249.734,68.541 245.988,69.536 246.923,69.536 247.859,69.536 248.794,69.536 249.734,69.536 245.988,70.532 246.923,70.532 247.859,70.532 248.794,70.532 249.734,70.532 246.892,117.634 247.828,117.634 248.763,117.634 249.699,117.634 250.639,117.634 246.892,118.629 247.828,118.629 248.763,118.629 249.699,118.629 250.639,118.629 246.892,119.624 247.828,119.624 248.763,119.624 249.699,119.624 250.639,119.624 246.892,120.62 247.828,120.62 248.763,120.62 249.699,120.62 250.639,120.62 246.892,121.615 247.828,121.615 248.763,121.615 249.699,121.615 250.639,121.615
D1L_P: C31.2 C33.2 C35.2 C37.2 C39.2 C41.2 C43.2 C45.2 C47.2 C49.2 C51.2 C53.2 C55.2 C57.2 D15.1 Q9.2 Q12.1 | length 4
  Bottom Layer w0.508: D15.1@56.381,108.06 56.622,107.819 Q12.1@60.249,107.819
  other v1: 63.412,90.31 64.457,90.31 65.502,90.31 66.547,90.31 63.412,91.245 64.457,91.245 65.502,91.245 66.547,91.245 63.412,92.181 64.457,92.181 65.502,92.181 66.547,92.181 63.412,93.117 64.457,93.117 65.502,93.117 66.547,93.117 63.471,94.052 64.496,94.052 65.522,94.052 66.547,94.052 63.353,99.189 64.398,99.189 65.443,99.189 66.488,99.189 63.353,100.125 64.398,100.125 65.443,100.125 66.488,100.125 63.353,101.061 64.398,101.061 65.443,101.061 66.488,101.061 63.353,101.996 64.398,101.996 65.443,101.996 66.488,101.996 63.412,102.932 64.437,102.932 65.463,102.932 66.488,102.932
D1L_S: D19.1 Q6.2 Q10.1 U2.2 | length 5.8
  Bottom Layer w0.508: D19.1@257.063,44.595 256.452,45.206 253.969,45.206 253.775,45.012 Q10.1@253.775,44.652 ; Q10.1@253.775,44.652 Q10.1@253.126,45.3 Q10.1@253.775,44.652
  other v1: 224.437,30.42 225.39,30.42 226.342,30.42 227.295,30.42 228.247,30.42 224.437,31.36 225.39,31.36 226.342,31.36 227.295,31.36 228.247,31.36 224.437,32.325 225.39,32.325 226.342,32.325 227.295,32.325 228.247,32.325 224.43,33.295 225.383,33.295 226.335,33.295 227.288,33.295 228.24,33.295 224.43,34.26 225.383,34.26 226.335,34.26 227.288,34.26 228.24,34.26 245.77,44.965 246.706,44.965 247.641,44.965 248.577,44.965 249.517,44.965 245.77,45.96 246.706,45.96 247.641,45.96 248.577,45.96 249.517,45.96 245.77,46.956 246.706,46.956 247.641,46.956 248.577,46.956 249.517,46.956 245.77,47.951 246.706,47.951 247.641,47.951 248.577,47.951 249.517,47.951 245.77,48.946 246.706,48.946 247.641,48.946 248.577,48.946 249.517,48.946 245.652,57.059 246.588,57.059 247.523,57.059 248.459,57.059 249.399,57.059 245.652,58.054 246.588,58.054 247.523,58.054 248.459,58.054 249.399,58.054 245.652,59.05 246.588,59.05 247.523,59.05 248.459,59.05 249.399,59.05 245.652,60.045 246.588,60.045 247.523,60.045 248.459,60.045 249.399,60.045 245.652,61.04 246.588,61.04 247.523,61.04 248.459,61.04 249.399,61.04
D2L_P: D22.1 Q8.2 Q13.1 U15.1 | length 4
  Bottom Layer w0.508: D22.1@56.345,57.26 Q13.1@60.355,57.26
  other v1: 76.055,29.937 77.007,29.937 77.96,29.937 78.912,29.937 79.865,29.937 76.055,30.877 77.007,30.877 77.96,30.877 78.912,30.877 79.865,30.877 76.055,31.842 77.007,31.842 77.96,31.842 78.912,31.842 79.865,31.842 63.081,41.135 64.126,41.135 65.171,41.135 66.216,41.135 63.081,42.091 64.126,42.091 65.171,42.091 66.216,42.091 63.081,43.027 64.126,43.027 65.171,43.027 66.216,43.027 63.081,43.962 64.126,43.962 65.171,43.962 66.216,43.962 63.081,44.898 64.126,44.898 65.171,44.898 66.216,44.898 63.14,45.834 64.165,45.834 65.191,45.834 66.216,45.834
D2L_S: C32.1 C34.1 C36.1 C38.1 C40.1 C42.1 C44.1 C46.1 C48.1 C50.1 C52.1 C54.1 C56.1 C58.1 D27.1 Q7.2 Q11.1 | length 4
  Bottom Layer w0.508: Q11.1@253.126,95.859 255.008,95.859 255.326,95.541 256.109,95.541 D27.1@256.745,94.905
  other v1: 245.96,95.643 246.896,95.643 247.831,95.643 248.767,95.643 249.707,95.643 245.96,96.639 246.896,96.639 247.831,96.639 248.767,96.639 249.707,96.639 245.96,97.634 246.896,97.634 247.831,97.634 248.767,97.634 249.707,97.634 245.96,98.629 246.896,98.629 247.831,98.629 248.767,98.629 249.707,98.629 245.96,99.625 246.896,99.625 247.831,99.625 248.767,99.625 249.707,99.625
DOUT_I_DC_SEC: C93.1 J2.100 R92.2 TP13.1 | length 463.1
  Top Layer w0.254: J2.100@10.069,35.779 10.186,35.662 12.356,35.662 12.755,35.263 v1(12.755,28.54) 12.755,26.649 8.742,22.636 8.742,12.533 12.26,9.015 12.261,9.015 17.045,4.231 23.21,4.231 23.501,4.523 279.657,4.523 294.38,19.246 294.38,105.708 294.386,105.714 294.386,106.195 294.38,106.2 294.38,132.54 279.694,147.226 v1(279.694,148.181) 280.415,148.903 TP13.1@282.08,148.903
  Bottom Layer w0.254: C93.1@12.449,29.796 12.755,29.49 v1(12.755,28.54) ; R92.2@278.3,148.181 v1(279.694,148.181)
DOUT_V_BATT_SEC: C107.1 J2.99 R116.2 TP14.1 | length 474.8
  Top Layer w0.254: J2.99@6.669,35.779 7.639,35.779 7.757,35.662 v1(7.823,35.662) ; v1(8.266,32.623) 8.266,32.561 8.636,32.191 8.636,28.404 7.239,27.007 7.239,12.26 15.274,4.225 15.281,4.225 16.181,3.325 72.163,3.325 72.696,2.792 82.28,2.792 82.813,3.325 280.525,3.325 295.74,18.54 295.74,27.978 295.165,28.553 295.165,29.033 295.74,29.608 295.74,134.703 295.728,134.703 284.381,146.05 284.381,154.15 283.043,155.488 282.987,155.488 282.259,156.216 TP14.1@282.259,156.726 ; v1(280.16,157.46) 281.603,157.46 TP14.1@282.809,156.255 ; TP14.1@282.067,156.918 TP14.1@282.225,157.076
  Bottom Layer w0.254: C107.1@6.756,34.671 7.788,34.671 7.823,34.707 ; v1(7.823,35.662) 7.823,34.707 ; v1(8.266,32.623) 8.266,33.309 7.823,33.752 7.823,34.707 ; R116.2@278.62,157.4 278.68,157.46 v1(280.16,157.46)
DOUT_V_DC_SEC: C108.1 J2.103 R117.2 TP15.1 | length 486.2
  Top Layer w0.254: J2.103@6.608,34.24 J2.103@6.669,34.179 4.309,34.179 3.889,33.759 v1(3.889,31.632) 3.889,27.385 6.163,25.111 6.163,11.217 15.261,2.119 281.294,2.119 297.16,17.985 297.16,136.08 286.39,146.85 286.39,159.116 282.25,163.256 TP15.1@282.25,164.081 282.25,164.578 281.488,165.34 v1(279.871,165.34)
  Bottom Layer w0.254: v1(3.889,31.632) C108.1@5.166,31.632 ; R117.2@278.34,165.44 278.44,165.34 v1(279.871,165.34)
dVdT_EFUSE: R78.2 U4.12 | length 4
  Bottom Layer w0.254: R78.2@8.713,112.922 8.382,113.253 8.382,114.819 8.837,115.274 8.837,115.964 8.932,116.059 U4.12@8.932,116.587
EN_RELAY_N: J2.94 R48.1 | length 558
  Top Layer w0.254: J2.94@10.069,38.179 12.574,38.179 12.78,37.972 12.78,37.309 13.518,36.571 15.108,36.571 16.098,35.581 16.098,31.321 v1(15.782,31.005) ; v1(215.06,176.417) 215.06,176.467 216.123,177.53 v1(216.123,177.58)
  Inner Layer1 w0.254: v1(72.75,3.558) 72.797,3.511 73.071,3.511 73.223,3.36 73.834,3.36 74.347,2.848 75.911,2.848 76.092,3.028 78.823,3.028 79.003,2.848 80.269,2.848 80.746,3.325 80.996,3.325 v1(81.043,3.372)
  Bottom Layer w0.254: v1(15.782,31.005) 15.782,18.951 22.038,12.695 22.538,12.695 31.804,3.429 72.554,3.429 72.684,3.558 v1(72.75,3.558) ; v1(81.043,3.372) 83.526,0.889 281.659,0.889 297.66,16.89 297.66,160.807 280.887,177.58 v1(216.123,177.58) ; v1(215.06,176.417) 215.127,176.417 215.383,176.16 R48.1@218,176.16
EN_RELAY_P: J2.92 R39.1 | length 593.3
  Top Layer w0.254: J2.92@10.069,38.979 10.192,38.856 12.543,38.856 13.237,38.162 13.237,37.515 13.724,37.028 15.298,37.028 16.556,35.77 16.556,35.667 16.575,35.647 16.575,30.728 16.376,30.529 16.376,29.642 v1(16.399,29.619)
  Inner Layer1 w0.254: v1(73.463,3.94) 74.036,3.94 74.614,3.362 75.779,3.362 75.902,3.485 79.012,3.485 79.153,3.344 79.992,3.344 80.6,3.952 81.505,3.952 v1(82.063,3.395)
  Bottom Layer w0.254: v1(16.399,29.619) 16.399,19.482 22.12,13.761 22.602,13.761 32.477,3.886 70.918,3.886 71.194,4.162 73.174,4.162 73.396,3.94 v1(73.463,3.94) ; v1(82.063,3.395) 83.857,1.6 280.234,1.6 296.62,17.986 296.62,160.027 279.648,177 172.38,177 R39.1@172.24,177.14
FAN_CTL: J2.60 R1.1 R4.1 | length 324.4
  Top Layer w0.254: v1(8.928,46.317) 8.975,46.364 8.975,46.747 9.138,46.91 9.138,48.166 9.138,48.993 9.138,51.366 9.429,51.656 9.946,51.656 J2.60@10.069,51.779 ; v1(10.668,22.504) 10.668,18.001 10.48,17.813 10.48,13.376 19.168,4.688 22.19,4.688 23.851,6.35 23.851,9.228 24.773,10.15 v1@33.069,10.15
  Inner Layer1 w0.254: v1@33.069,10.15 276.75,10.15 278.76,12.16 v1(278.76,13.68)
  Bottom Layer w0.254: v1(8.928,46.317) 8.928,46.251 9.238,45.941 9.238,37.148 14.913,31.474 14.913,25.51 14.565,25.162 13.326,25.162 v1(10.668,22.504) ; v1(278.76,13.68) 279.28,14.2 R4.1@280.54,14.2
  other v1: 33.062,10.143
G1H_P: Q9.4 R209.2 R216.2 U29.7 | length 25.3
  Bottom Layer w0.254: U29.7@38.866,92.97 39.391,92.97 39.564,92.797 39.564,92.755 40.455,91.864 47.998,91.864 48.362,92.227 50.503,92.227 R209.2@51.883,93.608
  Bottom Layer w1.27: R209.2@51.883,93.608 R209.2@51.883,93.883 51.883,95.093 R216.2@51.883,96.611 ; R216.2@52.15,95.859 Q9.4@60.249,95.859
G1H_S: Q6.4 R272.2 R275.2 U34.7 | length 23.7
  Bottom Layer w0.254: R272.2@258.249,59.486 258.772,60.009 258.772,60.398 259.282,60.908 262.541,60.908 264.271,62.638 271.287,62.638 271.95,61.975 U34.7@272.475,61.975
  Bottom Layer w1.27: Q6.4@253.126,57.26 253.214,57.347 258.157,57.347 258.249,57.255 R275.2@258.249,56.98 ; R275.2@258.249,57.245 R272.2@258.249,59.486
G1L_P: Q12.4 R215.2 R218.2 U30.7 | length 28
  Bottom Layer w0.254: U30.7@38.765,121.211 39.29,121.211 40.055,120.446 47.08,120.446 49.271,118.254 49.578,118.254 50.191,117.641 50.191,116.28 50.803,115.668 53.59,115.668 53.967,116.045 53.967,116.4 R215.2@54.49,116.923
  Bottom Layer w1.27: R215.2@54.49,116.923 54.49,117.031 54.492,117.033 R218.2@54.508,119.507 ; 54.492,118.202 54.716,117.979 Q12.4@60.249,117.979
G1L_S: Q10.4 R274.2 R277.2 U35.7 | length 24.5
  Bottom Layer w0.254: R274.2@258.205,36.68 258.728,37.203 258.728,37.494 259.169,37.935 261.892,37.935 262.14,37.687 262.14,36.486 263.051,35.575 265.414,35.575 266.347,34.642 266.347,34.468 266.595,34.22 271.137,34.22 271.777,33.58 271.777,33.5 271.95,33.328 U35.7@272.475,33.328
  Bottom Layer w1.27: Q10.4@253.126,35.14 257.403,35.14 ; R277.2@258.205,34.191 R274.2@258.205,36.68
G2H_P: Q8.4 R316.2 R319.2 U37.7 | length 29.3
  Bottom Layer w0.254: U37.7@38.905,35.665 39.43,35.665 40.096,34.999 46.698,34.999 47.794,36.095 47.794,38.55 49.307,40.063 53.957,40.063 54.611,40.717 54.641,40.717 55.164,41.24 R316.2@55.164,41.515
  Bottom Layer w1.27: R316.2@55.164,41.515 55.154,41.525 55.154,44.021 R319.2@55.145,44.031 55.16,44.046 55.16,44.345 56.051,45.236 60.291,45.236 Q8.4@60.355,45.3
G2H_S: Q7.4 R368.2 R371.2 U40.7 | length 27.2
  Bottom Layer w0.254: R368.2@258.753,111.547 258.753,111.822 259.276,112.345 259.284,112.345 259.945,113.006 262.493,113.006 263.902,114.416 263.902,117.3 264.783,118.181 271.032,118.181 271.302,117.911 U40.7@272.475,117.911
  Bottom Layer w1.27: Q7.4@253.126,107.819 253.312,108.004 255.956,108.004 256.715,108.763 257.267,108.763 257.269,108.766 258.735,108.766 258.75,108.781 R371.2@258.75,108.92 258.752,108.922 258.752,111.546 R368.2@258.753,111.547
G2L_P: Q13.4 R318.2 R321.2 U38.7 | length 24.2
  Bottom Layer w0.254: U38.7@38.866,64.737 39.391,64.737 40.247,63.88 51.481,63.88 53.152,65.551 53.745,65.551 R318.2@54.034,65.84
  Bottom Layer w1.27: R318.2@54.034,65.84 54.034,67.372 54.082,67.42 Q13.4@60.355,67.42
G2L_S: Q11.4 R370.2 R373.2 U41.7 | length 24.2
  Bottom Layer w0.254: R370.2@258.247,87.601 258.77,88.124 258.77,88.463 259.182,88.875 263.891,88.875 265.948,90.932 270.939,90.932 271.555,90.317 271.555,90.227 271.93,89.851 U41.7@272.455,89.851
  Bottom Layer w1.27: Q11.4@253.126,85.699 253.312,85.513 256.065,85.513 256.086,85.492 258.25,85.492 258.265,85.477 R373.2@258.265,85.202 258.256,85.211 258.256,87.311 258.247,87.32 R370.2@258.247,87.601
